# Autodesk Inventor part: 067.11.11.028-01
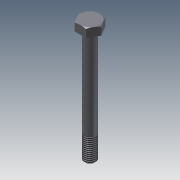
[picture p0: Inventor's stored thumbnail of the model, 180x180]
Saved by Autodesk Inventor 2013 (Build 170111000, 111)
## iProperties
Shininess: 64.0
Angle Display Precision: 2
Document Length Units: 11269
Document Angle Units: 11279
Document Time Units: 11290
Document Mass Units: 11283
Document Length Units Precision: 3
Document Angle Units Precision: 2
Created: 2003-03
Part Number: 067.11.11.028-01
Document SubType Name: Modeling
Designer: HKostya
Material: Steel, Mild
Density: 7.86 g/cm^3
Density: 0.0
Volumn: 0.0
Area: 0.0
PropertySet Name: Model Information
Control State: 0
Master: False
Checked Out: False
Checked Out Date: 2008-10-15
Last Check In Date: 2008-10-15
Author: HKostya
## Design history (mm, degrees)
sketch "Sketch3"
  geometry: L1 (0, 13.407)-(0, 23.407); L2 (0, 23.407)-(5.774, 23.407); L3 (5.774, 23.407)-(0, 13.407); L4 (0, 9.815)-(0, 0) reference; L5 (129, 4.907)-(-21.5, 4.907) reference
  constraints: 6 end point, 1 horizontal, 1 vertical
  dimensions: "d12" = 10 distance of L1.start L1.end; "d13" = 30 deg angle of L1 L3; "d14" = 0 distance between parallel lines of L1 L4; "d15" = 8.5 distance from line of L5 L1.start
body "Solid1"
sketch "Sketch1"
  geometry: C1 r 5 at (-15.306, 10.482)
  constraints: 1 centre point, 1 other
  dimensions: "d0" = 10 diameter of C1
sketch "Sketch2"
  geometry: L1 (4.907, -8.5)-(-4.907, -8.5); L2 (-4.907, -8.5)-(-9.815, 0); L3 (-9.815, 0)-(-4.907, 8.5); L4 (-4.907, 8.5)-(4.907, 8.5); L5 (4.907, 8.5)-(9.815, 0); L6 (9.815, 0)-(4.907, -8.5); C1 r 5 at (0, 0) reference; 1 further point
  constraints: 12 end point, 1 coincident, 1 horizontal, 11 other
  dimensions: "d3" = 17 distance between parallel lines of L5 L2
extrude "Extrusion1" new body sketch "Sketch1" distance "d1" = 100; taper "d2" = 0 deg
extrude "Extrusion2" join sketch "Sketch2" distance "d4" = 7.5; taper "d5" = 0 deg
chamfer "Chamfer1" distance "d6" = 1.6; stored, may be unused: second distance "d7" = 1.6, angle "d17" = 45 deg
fillet "Fillet1" dims "d8" = 0.2
thread "Thread1" dims "d9" = 20, "d10" = 0
workplane "Work Plane1"
workaxis "Work Axis1"
revolve "Revolution1" stored, may be unused: angle "d16" = 90 deg
other parameters: "d11" = -8.5
